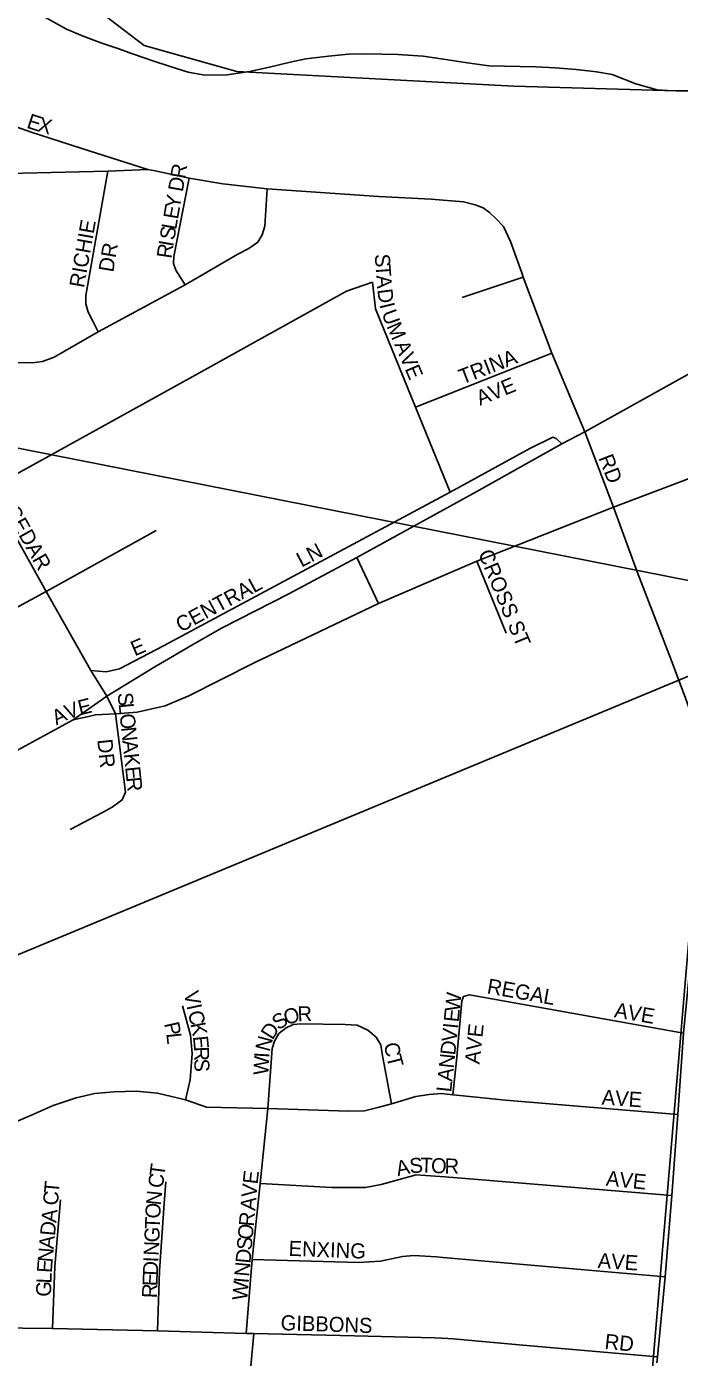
# Model space of a CAD drawing. Extents: x -209 to 4852, y 0 to 905.
# Drawn here: x 486 to 494.21, y 254.75 to 271.47 of the extents above; entities that cross this region are included whole.
import ezdxf

# ---------------------------------------------------------------- set-up
doc = ezdxf.new("R2010")
doc.units = 0
for name, color, linetype in [('GM_X_Airport_Location_Class_2', 7, 'Continuous'), ('GM_X_Airport_Location_Class_3', 7, 'Continuous'), ('GM_X_Major_Lake', 7, 'Continuous'), ('GM_X_Minor_River', 7, 'Continuous'), ('GM_X_US_Route', 7, 'Continuous')]:
    doc.layers.add(name, color=color, linetype=linetype)

msp = doc.modelspace()

# ---------------------------------------------------------------- linework, layer by layer
at = {"layer": 'GM_X_Airport_Location_Class_2'}
for points in [[(487.619, 269.661), (487.529, 269.68), (486.789, 269.912), (486.061, 270.147), (485.582, 270.314), (485.245, 270.484), (484.988, 270.652), (484.656, 270.978), (484.38, 271.342), (484.188, 271.694)], [(483.753, 269.599), (484.865, 269.609), (485.957, 269.634), (487.024, 269.659), (487.529, 269.68)], [(486.905, 267.639), (486.831, 267.783), (486.779, 267.886), (486.751, 267.989), (486.747, 268.096), (487.024, 269.659)], [(492.229, 268.379), (492.086, 268.774), (491.998, 268.961), (491.902, 269.063), (491.824, 269.138), (491.744, 269.199), (491.643, 269.236), (491.496, 269.271), (491.092, 269.306), (490.433, 269.338), (489.027, 269.434), (488.472, 269.498), (488.047, 269.57), (487.619, 269.661)], [(487.997, 268.231), (487.882, 268.415), (487.85, 268.498), (487.855, 268.584), (488.047, 269.57)], [(484.874, 266.87), (485.27, 267.108), (485.601, 267.255), (486.08, 267.25), (486.203, 267.267), (486.35, 267.321), (486.905, 267.639), (487.997, 268.231), (488.661, 268.613), (488.8, 268.687), (488.91, 268.767), (488.967, 268.856), (488.998, 268.968), (489.027, 269.434)], [(499.039, 269.433), (498.82, 269.408), (498.535, 269.368), (498.316, 269.287), (496.865, 268.521), (496.314, 268.203), (495.685, 267.845), (494.867, 267.41), (493.022, 266.382), (492.734, 266.23), (491.663, 265.631), (490.157, 264.802), (489.301, 264.346), (488.465, 263.919), (488.131, 263.73), (487.615, 263.43), (487.011, 263.062), (486.588, 262.763)], [(492.955, 266.543), (492.607, 267.372), (492.249, 268.326), (492.229, 268.379)], [(476.34, 260.572), (477.651, 261.298), (478.957, 262.033), (480.28, 262.754), (481.595, 263.479), (482.881, 264.196), (484.137, 264.883), (485.53, 265.664), (488.094, 267.077), (490.027, 268.15), (490.355, 268.262)], [(491.33, 265.623), (490.892, 266.694), (490.39, 267.928), (490.355, 268.262)], [(491.482, 268.069), (492.249, 268.326)], [(490.892, 266.694), (492.607, 267.372)], [(487.944, 263.022), (488.042, 263.064), (488.867, 263.482), (490.427, 264.226), (491.663, 264.759), (493.382, 265.437), (495.163, 266.11), (495.615, 266.463), (496.18, 266.947), (496.372, 267.126)], [(487.123, 262.838), (487.011, 263.062), (486.813, 263.384), (486.25, 264.375), (485.53, 265.664), (484.883, 266.834)], [(493.382, 265.437), (493.022, 266.382), (492.955, 266.543)], [(486.813, 263.384), (487.003, 263.365), (487.173, 263.405), (487.727, 263.695), (491.33, 265.623), (492.333, 266.175), (492.62, 266.317), (492.664, 266.297), (492.734, 266.23)], [(493.926, 254.683), (493.935, 254.759), (494.031, 255.765), (494.117, 256.788), (494.193, 257.807), (494.263, 258.828), (494.468, 260.925), (494.551, 261.914), (494.556, 262.043), (494.543, 262.213), (494.473, 262.515), (494.285, 263.05), (494.088, 263.573), (493.68, 264.623), (493.382, 265.437)], [(473.765, 257.477), (474.622, 257.958), (475.467, 258.428), (476.327, 258.902), (477.05, 259.289), (478.369, 260.022), (479.664, 260.743), (480.994, 261.473), (482.302, 262.203), (483.598, 262.904), (484.842, 263.614), (486.25, 264.375), (487.634, 265.143)], [(490.427, 264.226), (490.157, 264.802)], [(492.033, 263.853), (491.663, 264.759)], [(486.782, 262.807), (486.87, 262.827), (487.123, 262.838), (487.395, 262.861), (487.745, 262.938), (487.944, 263.022)], [(480.398, 259.351), (480.442, 259.375), (481.761, 260.14), (483.048, 260.855), (484.371, 261.549), (485.618, 262.236), (486.588, 262.763), (486.782, 262.807)], [(486.554, 261.384), (486.96, 261.601), (487.081, 261.668), (487.204, 261.758), (487.247, 261.854), (487.123, 262.838)], [(488.004, 257.989), (488.06, 258.24), (488.086, 258.571), (488.063, 258.8), (487.963, 259.171)], [(491.363, 258.053), (491.41, 258.482), (491.475, 259.229), (491.499, 259.288), (491.571, 259.307)], [(491.571, 259.307), (494.263, 258.828)], [(489.037, 257.879), (489.093, 258.634), (489.122, 258.728), (489.177, 258.824), (489.268, 258.895), (489.356, 258.934), (489.452, 258.944), (490.011, 258.936), (490.162, 258.927), (490.296, 258.865), (490.4, 258.776), (490.456, 258.68), (490.476, 258.569), (490.592, 257.941)], [(485.653, 257.622), (486.074, 257.803), (486.338, 257.917), (486.629, 258.015), (486.861, 258.068), (487.104, 258.09), (487.381, 258.099), (487.65, 258.073), (488.004, 257.989), (488.267, 257.897), (488.456, 257.892), (489.037, 257.879), (490.051, 257.846), (490.251, 257.851), (490.421, 257.895), (490.592, 257.941), (490.896, 258.032), (491.067, 258.058), (491.22, 258.069), (491.363, 258.053), (491.411, 258.048)], [(491.411, 258.048), (492.025, 257.987), (494.193, 257.807)], [(488.766, 255.055), (488.841, 255.982), (488.942, 256.937), (489.037, 257.879)], [(488.942, 256.937), (489.84, 256.89), (490.265, 256.888), (490.46, 256.927), (490.63, 256.972), (490.901, 257.046), (491.263, 257.024), (491.523, 257.002)], [(491.523, 257.002), (494.117, 256.788)], [(487.652, 255.086), (487.676, 255.842), (487.732, 256.688), (487.753, 256.959)], [(486.331, 255.116), (486.359, 255.895), (486.432, 256.734)], [(488.841, 255.982), (490.179, 255.947), (490.453, 255.964), (490.73, 256.019), (490.873, 256.032), (491.159, 256.017), (491.237, 256.01)], [(491.237, 256.01), (494.031, 255.765)], [(484.487, 255.138), (485.203, 255.13), (486.331, 255.116), (487.652, 255.086), (488.766, 255.055), (488.861, 255.053), (490.125, 255.024), (491.134, 254.997), (491.301, 254.99)], [(488.297, 248.897), (488.412, 250.243), (488.679, 253.103), (488.786, 254.234), (488.861, 255.053)], [(491.301, 254.99), (491.369, 254.987), (492.245, 254.905), (493.935, 254.759)]]:
    msp.add_lwpolyline(points, dxfattribs=at)
at = {"layer": 'GM_X_Major_Lake'}
msp.add_lwpolyline([(486.242, 271.589), (486.505, 271.44), (486.715, 271.352), (486.949, 271.264), (487.152, 271.199), (487.348, 271.126), (487.605, 271.038), (487.808, 270.973), (488.034, 270.9), (488.246, 270.865), (488.527, 270.868), (488.808, 270.908), (489.06, 270.964), (489.319, 271.027), (489.517, 271.069), (489.799, 271.102), (490.05, 271.127), (490.27, 271.131), (490.672, 271.123), (490.99, 271.102), (491.247, 271.066), (491.52, 271.023), (491.815, 270.979), (492.406, 270.967), (492.649, 270.955), (492.914, 270.935), (493.171, 270.907), (493.368, 270.873), (493.662, 270.753), (493.933, 270.679), (494.123, 270.668), (494.328, 270.671)], dxfattribs=at)
at = {"layer": 'GM_X_Minor_River'}
for points in [[(473.615, 282.049), (483.896, 284.796), (485.141, 284.612), (485.156, 284.602), (486.185, 284.144), (486.909, 283.615), (487.254, 282.987), (487.5, 282.399), (487.803, 281.553), (488.009, 280.83), (487.861, 279.795), (487.341, 278.327), (486.498, 276.593), (486.015, 275.883), (485.417, 275.091), (485.5, 273.87), (486.637, 271.887), (487.481, 271.235), (488.649, 270.91), (492.13, 270.724), (495.483, 270.631), (494.708, 264.441), (472.433, 268.831)], [(494.708, 264.441), (515.439, 271.658), (513.823, 252.487), (492.971, 244.015)], [(472.433, 268.831), (494.708, 264.441), (492.971, 244.015), (470.722, 248.55), (471.59, 258.577), (474.545, 261.601), (472.208, 265.185)]]:
    msp.add_lwpolyline(points, close=True, dxfattribs=at)
at = {"layer": 'GM_X_US_Route'}
msp.add_lwpolyline([(472.428, 254.214), (476.935, 256.085), (482.207, 258.275), (485.625, 259.703), (494.227, 263.272), (503.696, 267.208), (504.46, 267.578), (505.135, 267.963), (505.564, 268.219)], dxfattribs=at)

# ---------------------------------------------------------------- texts
at = {"layer": 'GM_X_Airport_Location_Class_3'}
for s, height, rotation, p in [('E', 0.189, 341.8345, (485.994, 270.206)), ('X', 0.189, 344.5745, (486.13, 270.161)), ('R', 0.189, 80.1144, (487.995, 269.554)), ('D', 0.189, 80.1366, (487.967, 269.39)), ('Y', 0.189, 80.1389, (487.929, 269.177)), ('E', 0.189, 80.1455, (487.907, 269.045)), ('RICHIE', 0.1894, 79.9197, (486.726, 268.184)), ('L', 0.189, 80.1155, (487.884, 268.914)), ('S', 0.189, 80.1424, (487.861, 268.783)), ('DR', 0.1894, 80.5416, (487.094, 268.38)), ('R', 0.189, 81.6157, (487.825, 268.553)), ('I', 0.189, 80.2933, (487.847, 268.701)), ('S', 0.189, 274.1879, (490.38, 268.612)), ('T', 0.189, 274.1879, (490.39, 268.479)), ('A', 0.189, 274.1879, (490.4, 268.346)), ('D', 0.189, 277.3561, (490.413, 268.169)), ('I', 0.189, 283.6925, (490.439, 267.981)), ('U', 0.189, 290.029, (490.465, 267.878)), ('M', 0.189, 293.1972, (490.526, 267.711)), ('A', 0.189, 293.1972, (490.625, 267.481)), ('V', 0.189, 293.1972, (490.69, 267.328)), ('TRINA', 0.1894, 21.036, (491.482, 266.977)), ('E', 0.189, 293.1972, (490.756, 267.175)), ('AVE', 0.1894, 22.1689, (491.704, 266.709)), ('RD', 0.1894, 291.2529, (493.192, 266.056)), ('CEDAR', 0.1894, 299.2939, (485.726, 265.395)), ('LN', 0.1894, 27.8967, (489.461, 264.675)), ('CROSS ST', 0.1894, 292.4771, (491.678, 264.858)), ('CENTRAL', 0.1894, 28.3012, (487.944, 263.859)), ('E', 0.189, 23.2137, (487.364, 263.56)), ('E', 0.189, 13.9633, (486.675, 262.819)), ('S', 0.189, 275.939, (487.147, 263.098)), ('A', 0.189, 25.7245, (486.378, 262.692)), ('V', 0.189, 20.4742, (486.524, 262.763)), ('L', 0.189, 275.9118, (487.161, 262.965)), ('O', 0.189, 275.9256, (487.174, 262.833)), ('DR', 0.1894, 276.0054, (486.893, 262.514)), ('N', 0.189, 275.9256, (487.192, 262.667)), ('A', 0.189, 275.9256, (487.209, 262.501)), ('K', 0.189, 275.9256, (487.226, 262.335)), ('E', 0.189, 275.939, (487.243, 262.17)), ('R', 0.189, 275.9353, (487.257, 262.037)), ('REGAL', 0.1894, 349.9197, (491.784, 259.329)), ('V', 0.189, 282.0642, (487.979, 259.335)), ('W', 0.189, 83.9699, (491.449, 259.091)), ('I', 0.189, 282.0642, (488.014, 259.172)), ('R', 0.189, 2.4294, (489.414, 258.973)), ('AVE', 0.1894, 350.2226, (493.384, 259.029)), ('C', 0.189, 282.0625, (488.032, 259.091)), ('S', 0.189, 34.728, (489.171, 258.858)), ('O', 0.189, 16.6029, (489.267, 258.927)), ('E', 0.189, 83.9816, (491.435, 258.959)), ('P', 0.189, 282.4192, (487.732, 258.947)), ('K', 0.189, 281.1942, (488.063, 258.945)), ('D', 0.189, 57.4802, (489.095, 258.732)), ('V', 0.189, 83.9784, (491.409, 258.71)), ('I', 0.189, 83.9544, (491.426, 258.876)), ('AVE', 0.1894, 84.0969, (491.7, 258.431)), ('L', 0.189, 276.0777, (487.76, 258.822)), ('E', 0.189, 275.4714, (488.095, 258.786)), ('N', 0.189, 75.0362, (489.058, 258.585)), ('C', 0.189, 279.3665, (490.497, 258.696)), ('D', 0.189, 83.9767, (491.392, 258.544)), ('R', 0.189, 272.1858, (488.107, 258.656)), ('W', 0.189, 86.6523, (489.042, 258.295)), ('I', 0.189, 86.6442, (489.055, 258.512)), ('T', 0.189, 284.4413, (490.525, 258.531)), ('N', 0.189, 83.9567, (491.374, 258.379)), ('S', 0.189, 270.3825, (488.113, 258.508)), ('A', 0.189, 83.9784, (491.356, 258.213)), ('L', 0.189, 83.9795, (491.342, 258.08)), ('AVE', 0.1894, 356.0499, (493.23, 257.93)), ('T', 0.189, 82.4105, (487.736, 257.02)), ('A', 0.189, 12.5359, (490.67, 257.029)), ('S', 0.189, 5.1969, (490.826, 257.064)), ('T', 0.189, 357.978, (490.952, 257.076)), ('O', 0.189, 357.7697, (491.086, 257.071)), ('R', 0.189, 359.4597, (491.258, 257.064)), ('C', 0.189, 82.4021, (487.716, 256.872)), ('E', 0.189, 83.4848, (488.908, 256.923)), ('AVE', 0.1894, 354.0969, (493.282, 256.913)), ('C', 0.189, 84.722, (486.396, 256.656)), ('T', 0.189, 84.719, (486.41, 256.806)), ('N', 0.189, 84.0219, (487.692, 256.658)), ('V', 0.189, 84.8349, (488.893, 256.758)), ('O', 0.189, 87.2664, (487.684, 256.494)), ('A', 0.189, 84.8349, (488.878, 256.592)), ('A', 0.189, 84.7244, (486.376, 256.44)), ('T', 0.189, 87.5947, (487.679, 256.361)), ('R', 0.189, 84.821, (488.86, 256.393)), ('D', 0.189, 84.7244, (486.361, 256.275)), ('G', 0.189, 87.5947, (487.672, 256.195)), ('O', 0.189, 84.823, (488.845, 256.227)), ('A', 0.189, 84.7244, (486.345, 256.109)), ('N', 0.189, 87.5731, (487.665, 256.028)), ('S', 0.189, 84.8303, (488.833, 256.094)), ('ENXING', 0.1894, 357.8402, (489.296, 256.03)), ('N', 0.189, 84.9223, (486.331, 255.943)), ('I', 0.189, 87.5959, (487.661, 255.945)), ('D', 0.189, 84.823, (488.818, 255.928)), ('AVE', 0.1894, 356.0569, (493.181, 255.879)), ('E', 0.189, 86.3367, (486.322, 255.811)), ('D', 0.189, 87.5834, (487.654, 255.778)), ('N', 0.189, 84.823, (488.803, 255.763)), ('G', 0.189, 87.4639, (486.309, 255.512)), ('L', 0.189, 87.4908, (486.316, 255.679)), ('R', 0.189, 87.5948, (487.642, 255.495)), ('E', 0.189, 87.5793, (487.649, 255.645)), ('W', 0.189, 84.8314, (488.776, 255.464)), ('I', 0.189, 84.8254, (488.795, 255.68)), ('GIBBONS', 0.1894, 358.1231, (489.196, 255.096)), ('RD', 0.1894, 353.9934, (493.265, 254.863))]:
    msp.add_text(s, height=height, rotation=rotation, dxfattribs=at).set_placement(p)

doc.saveas('drawing.dxf')
